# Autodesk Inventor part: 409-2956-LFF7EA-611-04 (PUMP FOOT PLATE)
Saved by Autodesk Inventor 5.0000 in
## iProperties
Created: 2010-06
Part Number: 409-2956-LFF7EA-611-04 (PUMP FOOT PLATE)
Cost Center: 0 lbmass
Material: A36 STEEL PLATE
Document SubType Name: Sheet Metal
Designer: S. Boerckel
Authority: 0 in^3
Mass: 1581.58 g
Surface Area: 388.996 cm^2
Volume: 201.219 cm^3
Density: 7.86 g/cm^3
Flat Pattern Width: 12.7 cm
Flat Pattern Length: 12.7 cm
Flat Pattern Area: 161.29 cm^2
Sheet Metal Rule: 1/2"Thk
Sheet Metal Width: 16.0000 in
Sheet Metal Length: 80.0000 in^2
Description: PUMP FOOT PLATE
User Status: BURN
SaveDate: 2008-01-15
SaveTime: 10:24
FileName: Sheet Metal
Wide: =<Flat Pattern Width>cm
Length: =<Flat Pattern Length>cm
Thickness: 0.5000 in
SMR: =<Sheet Metal Rule> - <Material>
Author: S. Boerckel
Revision Number: 0
Subject: DEMIN WATER FORWARDING PUMP SKID-7EA
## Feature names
1. Hole1
2. Plate1
